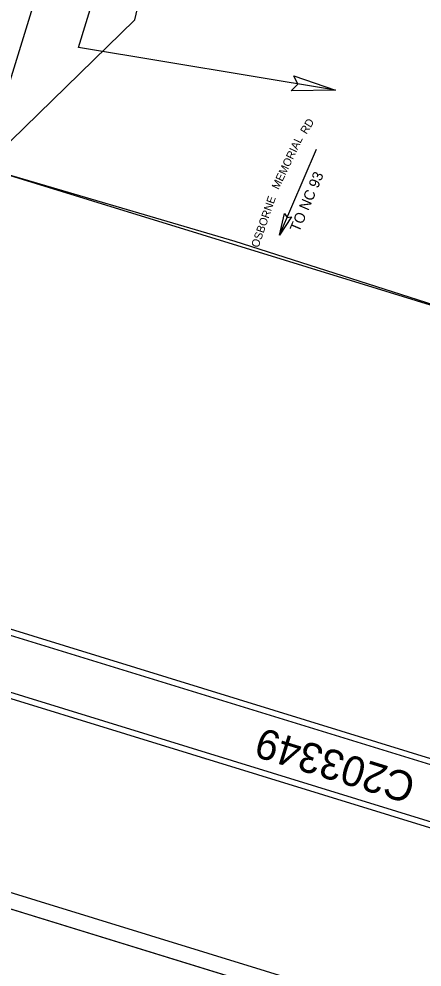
# Model space of a CAD drawing. Extents: x 1347947 to 1350662, y 1027710 to 1030532.
# Drawn here: x 1348486 to 1348821, y 1028346 to 1029133 of the extents above; entities that cross this region are included whole.
import ezdxf

# ---------------------------------------------------------------- set-up
doc = ezdxf.new("R2010")
doc.units = 0
for name, color, linetype in [('Default', 7, 'Continuous'), ('Prop Leader Line Medium', 7, 'Continuous'), ('Prop Terminator CELL', 7, 'Continuous'), ('Sheet Clip Boundary CELL', 7, 'Continuous'), ('Sheet Cutting Line CELL', 7, 'Continuous'), ('Sheet Data Field CELL', 7, 'Continuous'), ('Sheet Plot Border Inside CELL', 7, 'Continuous'), ('Sheet Plot Border Outside CELL', 7, 'Continuous'), ('Sheet Symbology CELL', 7, 'Continuous'), ('Sheet Title CELL', 7, 'Continuous')]:
    doc.layers.add(name, color=color, linetype=linetype)

msp = doc.modelspace()

# ---------------------------------------------------------------- linework, layer by layer
at = {"layer": 'Prop Leader Line Medium'}
for p, q in [((1348535.84, 1029109.78), (1348595.87, 1029304.7)), ((1348749.37, 1029074.27), (1348535.84, 1029109.78))]:
    msp.add_line(p, q, dxfattribs=at)
msp.add_lwpolyline([(1348456.59, 1029010.05), (1348681.97, 1029741.89), (1349133.09, 1029602.97), (1348907.71, 1028871.13)], close=True, dxfattribs=at)
at = {"layer": 'Prop Terminator CELL'}
for points in [[(1348714.78, 1029086.03), (1348749.37, 1029074.27), (1348712.61, 1029073.62), (1348718.16, 1029079.22)], [(1348712.85, 1028969.09), (1348702.93, 1028953.76), (1348707.1, 1028971.66), (1348709.14, 1028968.29)]]:
    msp.add_lwpolyline(points, close=True, dxfattribs=at)
at = {"layer": 'Sheet Clip Boundary CELL'}
msp.add_lwpolyline([(1348456.59, 1029010.05), (1348582.47, 1029132.61), (1348611.5, 1029255.07), (1348756.63, 1029710.8), (1349133.09, 1029602.97), (1349132.8, 1029579.86), (1349058.53, 1029368.75), (1348907.71, 1028871.13), (1348666.12, 1028948.43)], close=True, dxfattribs=at)
at = {"layer": 'Sheet Cutting Line CELL'}
msp.add_line((1347946.88, 1028557.97), (1348998.14, 1028234.22), dxfattribs=at)
at = {"layer": 'Sheet Plot Border Inside CELL'}
msp.add_lwpolyline([(1348980.53, 1028253.25), (1349471, 1029845.94), (1348462.64, 1030156.47), (1347972.16, 1028563.78)], close=True, dxfattribs=at)
at = {"layer": 'Sheet Plot Border Outside CELL'}
msp.add_lwpolyline([(1348442.51, 1030167.38), (1347946.88, 1028557.97), (1348998.14, 1028234.22), (1349493.77, 1029843.63)], close=True, dxfattribs=at)
at = {"layer": 'Sheet Symbology CELL'}
msp.add_line((1348702.93, 1028953.76), (1348733.62, 1029025.07), dxfattribs=at)
at = {"layer": 'Sheet Title CELL'}
for p, q in [((1348848.45, 1028512.61), (1348050.43, 1028758.36)), ((1349023.78, 1028453.38), (1348048.96, 1028753.59))]:
    msp.add_line(p, q, dxfattribs=at)
for points in [[(1348029.47, 1028707.27), (1349013.84, 1028404.13)], [(1348029.47, 1028707.27), (1349013.84, 1028404.13)], [(1348035.72, 1028710.59), (1349010.54, 1028410.38)]]:
    msp.add_lwpolyline(points, dxfattribs=at)

# ---------------------------------------------------------------- texts
at = {"layer": 'Default'}
for s, rotation, p in [('RD', 58.3753, (1348725.33, 1029037.07)), ('MEMORIAL', 64.62651, (1348702.08, 1028991.11)), ('OSBORNE', 70.83049, (1348685.35, 1028942.85))]:
    msp.add_text(s, height=6.65, rotation=rotation, dxfattribs=at).set_placement(p)
at = {"layer": 'Sheet Data Field CELL'}
msp.add_text('TO NC 93', height=8.75, rotation=66.8699, dxfattribs=at).set_placement((1348719.13, 1028955.63))
at = {"layer": 'Sheet Title CELL'}
msp.add_text('C203349', height=25, rotation=162.88342, dxfattribs=at).set_placement((1348817.64, 1028504.95))

doc.saveas('drawing.dxf')
